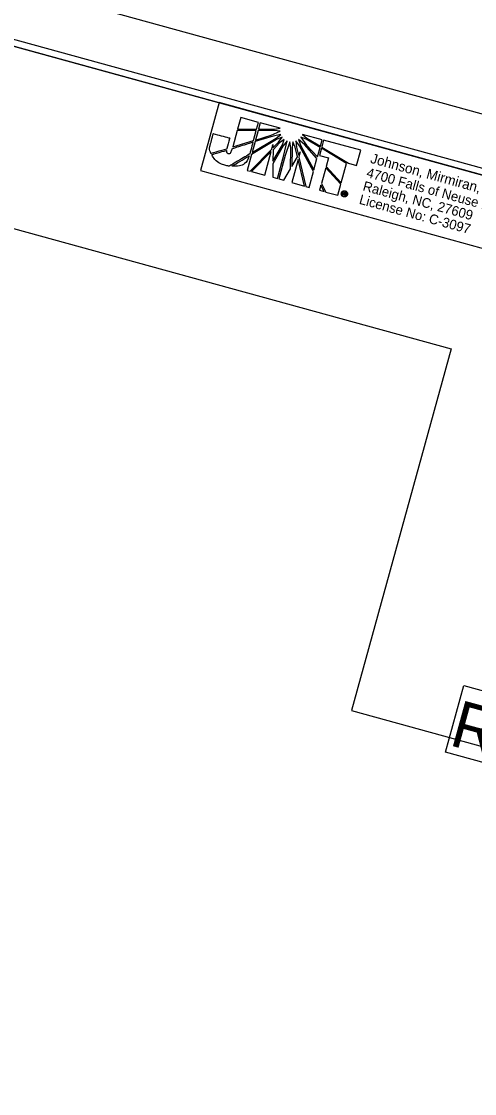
# Model space of a CAD drawing. Extents: x 1641192 to 2864602, y 841295 to 973236.
# Drawn here: x 1642670.1 to 1642843.9, y 842046.5 to 842457.9 of the extents above; entities that cross this region are included whole.
import ezdxf

# ---------------------------------------------------------------- set-up
doc = ezdxf.new("R2010")
doc.units = 0
for name, color, linetype in [('Prop Dimension Text', 7, 'Continuous'), ('Prop DSN White Annotation Label', 7, 'Continuous'), ('Sheet Clip Boundary CELL', 7, 'Continuous'), ('Sheet Plan CELL', 7, 'Continuous'), ('Sheet Plot Border Inside CELL', 7, 'Continuous'), ('Sheet Plot Border Outside CELL', 7, 'Continuous')]:
    doc.layers.add(name, color=color, linetype=linetype)

msp = doc.modelspace()

# ---------------------------------------------------------------- linework, layer by layer
at = {"layer": 'Prop Dimension Text'}
for p, q in [((1642754.19, 842421.06), (1642752.96, 842416.57)), ((1642760.96, 842419.21), (1642754.19, 842421.06)), ((1642752.96, 842416.57), (1642760.24, 842416.59)), ((1642760.24, 842416.59), (1642760.96, 842419.21)), ((1642761.67, 842419.05), (1642761.01, 842416.62)), ((1642761.01, 842416.62), (1642767.12, 842416.63)), ((1642769.3, 842416.96), (1642761.67, 842419.05)), ((1642767.12, 842416.63), (1642769.3, 842416.96)), ((1642752.82, 842416.06), (1642751.09, 842409.75)), ((1642760.11, 842416.1), (1642752.82, 842416.06)), ((1642767.91, 842412.64), (1642758.34, 842406.9)), ((1642758.54, 842407.62), (1642767.72, 842413.09)), ((1642759.03, 842412.18), (1642760.11, 842416.1)), ((1642766.59, 842413.97), (1642759.7, 842411.84)), ((1642760.87, 842416.1), (1642759.86, 842412.43)), ((1642759.86, 842412.43), (1642765.83, 842414.26)), ((1642766.97, 842416.11), (1642760.87, 842416.1)), ((1642765.83, 842414.26), (1642769.26, 842415.77)), ((1642769.53, 842414.56), (1642766.59, 842413.97)), ((1642769.26, 842415.77), (1642766.97, 842416.11)), ((1642767.72, 842413.09), (1642769.53, 842414.56)), ((1642770.09, 842413.53), (1642767.91, 842412.64)), ((1642768.66, 842411.59), (1642770.09, 842413.53)), ((1642770.89, 842412.66), (1642769.08, 842411.31)), ((1642770.13, 842410.63), (1642770.89, 842412.66)), ((1642776.35, 842412.69), (1642777.15, 842410.47)), ((1642778.61, 842410.67), (1642776.35, 842412.69)), ((1642777.23, 842413.58), (1642779.44, 842410.48)), ((1642779.25, 842412.74), (1642777.23, 842413.58)), ((1642785.42, 842412.5), (1642777.92, 842414.59)), ((1642777.92, 842414.59), (1642779.58, 842413.18)), ((1642784.61, 842409.55), (1642779.25, 842412.74)), ((1642779.58, 842413.18), (1642784.75, 842410.07)), ((1642784.75, 842410.07), (1642785.42, 842412.5)), ((1642785.95, 842412.39), (1642785.24, 842409.78)), ((1642800.19, 842408.49), (1642785.95, 842412.39)), ((1642751.09, 842409.75), (1642759.03, 842412.18)), ((1642757.78, 842400.45), (1642766.05, 842408.94)), ((1642759.7, 842411.84), (1642758.54, 842407.62)), ((1642766.05, 842408.94), (1642766.54, 842410.72)), ((1642770.41, 842410.14), (1642766.49, 842403.35)), ((1642766.52, 842404.35), (1642770.13, 842410.63)), ((1642766.55, 842408.71), (1642766.52, 842404.35)), ((1642766.54, 842409.4), (1642768.66, 842411.59)), ((1642766.54, 842410.72), (1642766.54, 842409.4)), ((1642769.08, 842411.31), (1642766.55, 842408.71)), ((1642771.93, 842412.06), (1642770.41, 842410.14)), ((1642770.75, 842406.64), (1642771.93, 842412.06)), ((1642773.04, 842411.75), (1642771.23, 842406.5)), ((1642773.34, 842409.34), (1642773.04, 842411.75)), ((1642773.25, 842401.37), (1642773.34, 842409.34)), ((1642773.84, 842409.53), (1642773.72, 842402.21)), ((1642774.21, 842411.76), (1642773.84, 842409.53)), ((1642775.05, 842409.68), (1642774.21, 842411.76)), ((1642775.93, 842406.02), (1642775.05, 842409.68)), ((1642775.34, 842412.09), (1642775.57, 842409.7)), ((1642776.76, 842410.22), (1642775.34, 842412.09)), ((1642775.57, 842409.7), (1642776.28, 842406.61)), ((1642782.04, 842400.34), (1642776.76, 842410.22)), ((1642777.15, 842410.47), (1642782.23, 842401.04)), ((1642783.42, 842405.37), (1642778.61, 842410.67)), ((1642779.44, 842410.48), (1642783.58, 842405.98)), ((1642783.58, 842405.98), (1642784.61, 842409.55)), ((1642785.09, 842409.25), (1642784.35, 842406.53)), ((1642785.11, 842409.3), (1642785.09, 842409.25)), ((1642794.78, 842403.43), (1642785.11, 842409.3)), ((1642785.24, 842409.78), (1642785.22, 842409.7)), ((1642785.22, 842409.7), (1642795.56, 842403.49)), ((1642798.59, 842402.66), (1642800.19, 842408.49)), ((1642758.34, 842406.9), (1642756.66, 842400.76)), ((1642765.78, 842407.96), (1642758.3, 842400.31)), ((1642763.35, 842398.92), (1642765.78, 842407.96)), ((1642768.28, 842397.61), (1642770.75, 842406.64)), ((1642771.23, 842406.5), (1642768.76, 842397.48)), ((1642773.72, 842402.21), (1642775.93, 842406.02)), ((1642776.19, 842404.91), (1642773.78, 842396.1)), ((1642778.62, 842394.77), (1642776.19, 842404.91)), ((1642776.28, 842406.61), (1642777, 842407.86)), ((1642777, 842407.86), (1642776.46, 842405.88)), ((1642776.46, 842405.88), (1642779.17, 842394.58)), ((1642782.23, 842401.04), (1642783.42, 842405.37)), ((1642784.35, 842406.53), (1642787.82, 842405.57)), ((1642787.82, 842405.57), (1642786.93, 842402.32)), ((1642756.66, 842400.76), (1642757.78, 842400.45)), ((1642758.3, 842400.31), (1642763.35, 842398.92)), ((1642766.49, 842403.35), (1642766.42, 842398.12)), ((1642770.64, 842396.96), (1642773.25, 842401.37)), ((1642780.37, 842394.26), (1642782.04, 842400.34)), ((1642786.78, 842401.76), (1642785.12, 842395.71)), ((1642792.58, 842395.43), (1642786.78, 842401.76)), ((1642786.93, 842402.32), (1642792.73, 842395.95)), ((1642792.73, 842395.95), (1642794.78, 842403.43)), ((1642795.56, 842403.49), (1642798.59, 842402.66)), ((1642766.42, 842398.12), (1642768.28, 842397.61)), ((1642768.76, 842397.48), (1642770.64, 842396.96)), ((1642773.78, 842396.1), (1642778.62, 842394.77)), ((1642779.17, 842394.58), (1642780.37, 842394.26)), ((1642784.94, 842395.05), (1642784.41, 842393.15)), ((1642784.41, 842393.15), (1642786.17, 842392.67)), ((1642786.17, 842392.67), (1642784.94, 842395.05)), ((1642785.12, 842395.71), (1642786.84, 842392.48)), ((1642786.84, 842392.48), (1642791.43, 842391.22)), ((1642791.43, 842391.22), (1642792.58, 842395.43)), ((1642793.39, 842391.37), (1642793.67, 842392.41)), ((1642793.67, 842392.41), (1642794.1, 842392.29)), ((1642793.85, 842392.15), (1642793.79, 842391.9)), ((1642793.79, 842391.9), (1642793.98, 842391.85)), ((1642794.04, 842392.1), (1642793.85, 842392.15)), ((1642793.98, 842391.85), (1642793.92, 842391.66)), ((1642793.92, 842391.66), (1642793.98, 842391.85)), ((1642793.98, 842391.85), (1642793.99, 842391.85)), ((1642794.1, 842392.29), (1642794.04, 842392.1)), ((1642794.04, 842392.1), (1642794.1, 842392.29)), ((1642794.07, 842392.09), (1642794.04, 842392.1)), ((1642794.1, 842392.29), (1642794.16, 842392.28)), ((1642794.26, 842392.91), (1642794.21, 842392.69)), ((1642794.21, 842392.69), (1642794.26, 842392.91)), ((1642793.62, 842391.31), (1642793.39, 842391.37)), ((1642793.74, 842391.71), (1642793.62, 842391.31)), ((1642793.7, 842390.85), (1642793.64, 842390.63)), ((1642793.64, 842390.63), (1642793.7, 842390.85)), ((1642793.65, 842390.63), (1642793.64, 842390.63)), ((1642793.7, 842390.85), (1642793.71, 842390.85)), ((1642793.92, 842391.66), (1642793.74, 842391.71)), ((1642793.93, 842391.66), (1642793.92, 842391.66))]:
    msp.add_line(p, q, dxfattribs=at)
msp.add_lwpolyline([(1642738.73, 842400.68), (1642883.38, 842360.88), (1642890.57, 842386.98), (1642745.92, 842426.79)], close=True, dxfattribs=at)
for points in [[(1642752.96, 842416.57), (1642760.24, 842416.59), (1642760.96, 842419.21), (1642754.19, 842421.06), (1642752.96, 842416.57)], [(1642767.12, 842416.63), (1642769.3, 842416.96), (1642761.67, 842419.05), (1642761.01, 842416.62), (1642767.12, 842416.63)], [(1642751.09, 842409.75), (1642759.03, 842412.18), (1642760.11, 842416.1), (1642752.82, 842416.06), (1642751.09, 842409.75)], [(1642770.09, 842413.53), (1642767.91, 842412.64), (1642758.34, 842406.9), (1642756.66, 842400.76), (1642757.78, 842400.45), (1642766.05, 842408.94), (1642766.54, 842410.72), (1642766.54, 842409.4), (1642768.66, 842411.59), (1642770.09, 842413.53)], [(1642759.7, 842411.84), (1642758.54, 842407.62), (1642767.72, 842413.09), (1642769.53, 842414.56), (1642766.59, 842413.97), (1642759.7, 842411.84)], [(1642760.87, 842416.1), (1642759.86, 842412.43), (1642765.83, 842414.26), (1642769.26, 842415.77), (1642766.97, 842416.11), (1642760.87, 842416.1)], [(1642770.89, 842412.66), (1642769.08, 842411.31), (1642766.55, 842408.71), (1642766.52, 842404.35), (1642770.13, 842410.63), (1642770.89, 842412.66)], [(1642776.35, 842412.69), (1642777.15, 842410.47), (1642782.23, 842401.04), (1642783.42, 842405.37), (1642778.61, 842410.67), (1642776.35, 842412.69)], [(1642777.23, 842413.58), (1642779.44, 842410.48), (1642783.58, 842405.98), (1642784.61, 842409.55), (1642779.25, 842412.74), (1642777.23, 842413.58)], [(1642779.58, 842413.18), (1642784.75, 842410.07), (1642785.42, 842412.5), (1642777.92, 842414.59), (1642779.58, 842413.18)], [(1642800.19, 842408.49), (1642785.95, 842412.39), (1642785.24, 842409.78), (1642785.22, 842409.7), (1642795.56, 842403.49), (1642798.59, 842402.66), (1642800.19, 842408.49)], [(1642770.41, 842410.14), (1642766.49, 842403.35), (1642766.42, 842398.12), (1642768.28, 842397.61), (1642770.75, 842406.64), (1642771.93, 842412.06), (1642770.41, 842410.14)], [(1642773.04, 842411.75), (1642771.23, 842406.5), (1642768.76, 842397.48), (1642770.64, 842396.96), (1642773.25, 842401.37), (1642773.34, 842409.34), (1642773.04, 842411.75)], [(1642774.21, 842411.76), (1642773.84, 842409.53), (1642773.72, 842402.21), (1642775.93, 842406.02), (1642775.05, 842409.68), (1642774.21, 842411.76)], [(1642775.34, 842412.09), (1642775.57, 842409.7), (1642776.28, 842406.61), (1642777, 842407.86), (1642776.46, 842405.88), (1642779.17, 842394.58), (1642780.37, 842394.26), (1642782.04, 842400.34), (1642776.76, 842410.22), (1642775.34, 842412.09)], [(1642785.11, 842409.3), (1642785.09, 842409.25), (1642784.35, 842406.53), (1642787.82, 842405.57), (1642786.93, 842402.32), (1642792.73, 842395.95), (1642794.78, 842403.43), (1642785.11, 842409.3)], [(1642758.3, 842400.31), (1642763.35, 842398.92), (1642765.78, 842407.96), (1642758.3, 842400.31)], [(1642773.78, 842396.1), (1642778.62, 842394.77), (1642776.19, 842404.91), (1642773.78, 842396.1)], [(1642786.78, 842401.76), (1642785.12, 842395.71), (1642786.84, 842392.48), (1642791.43, 842391.22), (1642792.58, 842395.43), (1642786.78, 842401.76), (1642786.78, 842401.76)], [(1642784.41, 842393.15), (1642784.41, 842393.15), (1642786.17, 842392.67), (1642784.94, 842395.05), (1642784.41, 842393.15)], [(1642794.33, 842391.38), (1642794.32, 842391.32), (1642794.32, 842391.28), (1642794.31, 842391.25), (1642794.3, 842391.12), (1642794.09, 842391.18)]]:
    msp.add_lwpolyline(points, dxfattribs=at)
for points, degree in [([(1642749.94, 842413.18), (1642749.94, 842413.18), (1642743.67, 842414.9), (1642743.67, 842414.9), (1642743.67, 842414.9), (1642742.6, 842410.98), (1642742.6, 842410.98), (1642742.6, 842410.98), (1642742.48, 842410.57), (1642742.48, 842410.57), (1642742.15, 842409.34), (1642742.28, 842408.26), (1642742.77, 842407.24), (1642742.77, 842407.24), (1642748.78, 842408.96), (1642748.8, 842409.04), (1642748.8, 842409.04), (1642749.94, 842413.18), (1642749.94, 842413.18)], 3), ([(1642749.36, 842407.27), (1642748.96, 842407.38), (1642748.68, 842407.7), (1642748.74, 842408.49), (1642748.74, 842408.49), (1642743.05, 842406.82), (1642743.05, 842406.82), (1642744.12, 842404.83), (1642746.25, 842403.24), (1642748.27, 842402.68), (1642748.8, 842402.54), (1642749.21, 842402.47), (1642749.8, 842402.43), (1642749.8, 842402.43), (1642757.63, 842407.06), (1642757.63, 842407.06), (1642757.63, 842407.06), (1642758.88, 842411.62), (1642758.88, 842411.62), (1642758.88, 842411.62), (1642750.93, 842409.18), (1642750.93, 842409.18), (1642750.46, 842407.47), (1642749.92, 842407.12), (1642749.36, 842407.27)], 3), ([(1642749.36, 842407.27), (1642748.96, 842407.38), (1642748.68, 842407.7), (1642748.74, 842408.49), (1642748.74, 842408.49), (1642743.05, 842406.82), (1642743.05, 842406.82), (1642744.12, 842404.83), (1642746.25, 842403.24), (1642748.27, 842402.68), (1642748.8, 842402.54), (1642749.21, 842402.47), (1642749.8, 842402.43), (1642749.8, 842402.43), (1642757.63, 842407.06), (1642757.63, 842407.06), (1642757.63, 842407.06), (1642758.88, 842411.62), (1642758.88, 842411.62), (1642758.88, 842411.62), (1642750.93, 842409.18), (1642750.93, 842409.18), (1642750.46, 842407.47), (1642749.92, 842407.12), (1642749.36, 842407.27)], 3), ([(1642757.44, 842406.35), (1642757.44, 842406.35), (1642750.67, 842402.35), (1642750.67, 842402.35), (1642753.43, 842402.28), (1642756.46, 842403.29), (1642757.44, 842406.35)], 3), ([(1642793.64, 842390.63), (1642793.33, 842390.71), (1642793.09, 842390.9), (1642792.92, 842391.19), (1642792.76, 842391.47), (1642792.72, 842391.77), (1642792.81, 842392.09), (1642792.89, 842392.41), (1642793.08, 842392.65), (1642793.37, 842392.8), (1642793.65, 842392.95), (1642793.94, 842392.99), (1642794.26, 842392.91)], 3), ([(1642794.21, 842392.69), (1642793.95, 842392.76), (1642793.71, 842392.73), (1642793.49, 842392.61), (1642793.26, 842392.48), (1642793.1, 842392.28), (1642793.03, 842392.03), (1642792.96, 842391.77), (1642793, 842391.52), (1642793.13, 842391.3), (1642793.25, 842391.07), (1642793.45, 842390.92), (1642793.7, 842390.85)], 3), ([(1642793.71, 842390.85), (1642793.97, 842390.78), (1642794.21, 842390.81), (1642794.43, 842390.94), (1642794.66, 842391.07), (1642794.82, 842391.27), (1642794.89, 842391.52), (1642794.96, 842391.77), (1642794.92, 842392.03), (1642794.79, 842392.25), (1642794.66, 842392.47), (1642794.47, 842392.62), (1642794.21, 842392.69)], 3), ([(1642793.99, 842391.85), (1642794.14, 842391.81), (1642794.22, 842391.83), (1642794.25, 842391.92), (1642794.27, 842391.99), (1642794.21, 842392.05), (1642794.07, 842392.09)], 3), ([(1642794.16, 842392.28), (1642794.43, 842392.2), (1642794.53, 842392.06), (1642794.47, 842391.86), (1642794.45, 842391.76), (1642794.39, 842391.7), (1642794.29, 842391.66)], 3), ([(1642794.26, 842392.91), (1642794.58, 842392.82), (1642794.83, 842392.63), (1642794.99, 842392.35), (1642795.16, 842392.08), (1642795.2, 842391.78), (1642795.11, 842391.46)], 3), ([(1642795.11, 842391.46), (1642795.02, 842391.14), (1642794.84, 842390.9), (1642794.56, 842390.73), (1642794.27, 842390.58), (1642793.97, 842390.54), (1642793.65, 842390.63)], 3), ([(1642794.1, 842391.57), (1642794.08, 842391.6), (1642794.03, 842391.63), (1642793.93, 842391.66)], 2), ([(1642794.09, 842391.18), (1642794.07, 842391.25), (1642794.07, 842391.31), (1642794.09, 842391.38), (1642794.12, 842391.48), (1642794.12, 842391.54), (1642794.1, 842391.57)], 3), ([(1642794.29, 842391.66), (1642794.34, 842391.61), (1642794.36, 842391.51), (1642794.33, 842391.38)], 2)]:
    msp.add_open_spline(points, degree=degree, dxfattribs=at)
at = {"layer": 'Prop DSN White Annotation Label'}
msp.add_lwpolyline([(1642839.77, 842203.05), (1643029.31, 842150.89), (1643022.29, 842125.36), (1642832.75, 842177.53)], close=True, dxfattribs=at)
at = {"layer": 'Sheet Clip Boundary CELL'}
for points in [[(1642834.84, 842332.26), (1642796.64, 842193.46), (1642979.12, 842143.25), (1642931.91, 841980.78), (1642684.68, 842016.94), (1642616.55, 841780.17), (1642867.94, 841712.2), (1642769.91, 841383), (1642620.74, 841424.05), (1642612.78, 841395.12), (1641412.11, 841725.54), (1641476.31, 841958.82), (1641627.07, 841958.82), (1641755.49, 842119.21), (1641752.38, 842181.83), (1641796.56, 842667.29)], [(1642584.62, 842450.42), (1642572.01, 842404.59), (1642834.84, 842332.26)]]:
    msp.add_lwpolyline(points, dxfattribs=at)
at = {"layer": 'Sheet Plan CELL'}
for points in [[(1643083.47, 842333.88), (1641637.2, 842731.89), (1641358.6, 841719.52), (1642804.85, 841321.52)], [(1641358.6, 841719.52), (1641637.16, 842731.87), (1642890.57, 842386.98), (1642850.76, 842242.29), (1643043.63, 842189.2), (1642804.85, 841321.52)]]:
    msp.add_lwpolyline(points, close=True, dxfattribs=at)
at = {"layer": 'Sheet Plot Border Inside CELL'}
msp.add_lwpolyline([(1641209.95, 841757.82), (1642816.23, 841315.8), (1643096.16, 842332.97), (1641489.87, 842775.01)], close=True, dxfattribs=at)
at = {"layer": 'Sheet Plot Border Outside CELL'}
msp.add_lwpolyline([(1641192.11, 841741.99), (1642815.27, 841295.31), (1643105.8, 842351.06), (1641482.64, 842797.74)], close=True, dxfattribs=at)
msp.add_lwpolyline([(1641192.11, 841741.99), (1642815.27, 841295.31), (1643105.8, 842351.06), (1641482.64, 842797.74)], close=True, dxfattribs=at)

# ---------------------------------------------------------------- texts
at = {"layer": 'Prop Dimension Text'}
for s, height, p in [('Johnson, Mirmiran, & Thompson Inc.', 3.8334, (1642803.65, 842403.71)), ('4700 Falls of Neuse Rd, Suite 100, ', 3.7239, (1642802.15, 842398.28)), ('Raleigh, NC, 27609', 3.7239, (1642800.74, 842393.15)), ('License No: C-3097', 3.7239, (1642799.33, 842388.02))]:
    msp.add_text(s, height=height, rotation=344.6135, dxfattribs=at).set_placement(p)
at = {"layer": 'Prop DSN White Annotation Label'}
msp.add_text('ROW CALLOUTS', height=18, rotation=344.6132, dxfattribs=at).set_placement((1642833.65, 842180.34))

doc.saveas('drawing.dxf')
